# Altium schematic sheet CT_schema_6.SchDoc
size 411 x 402 mm
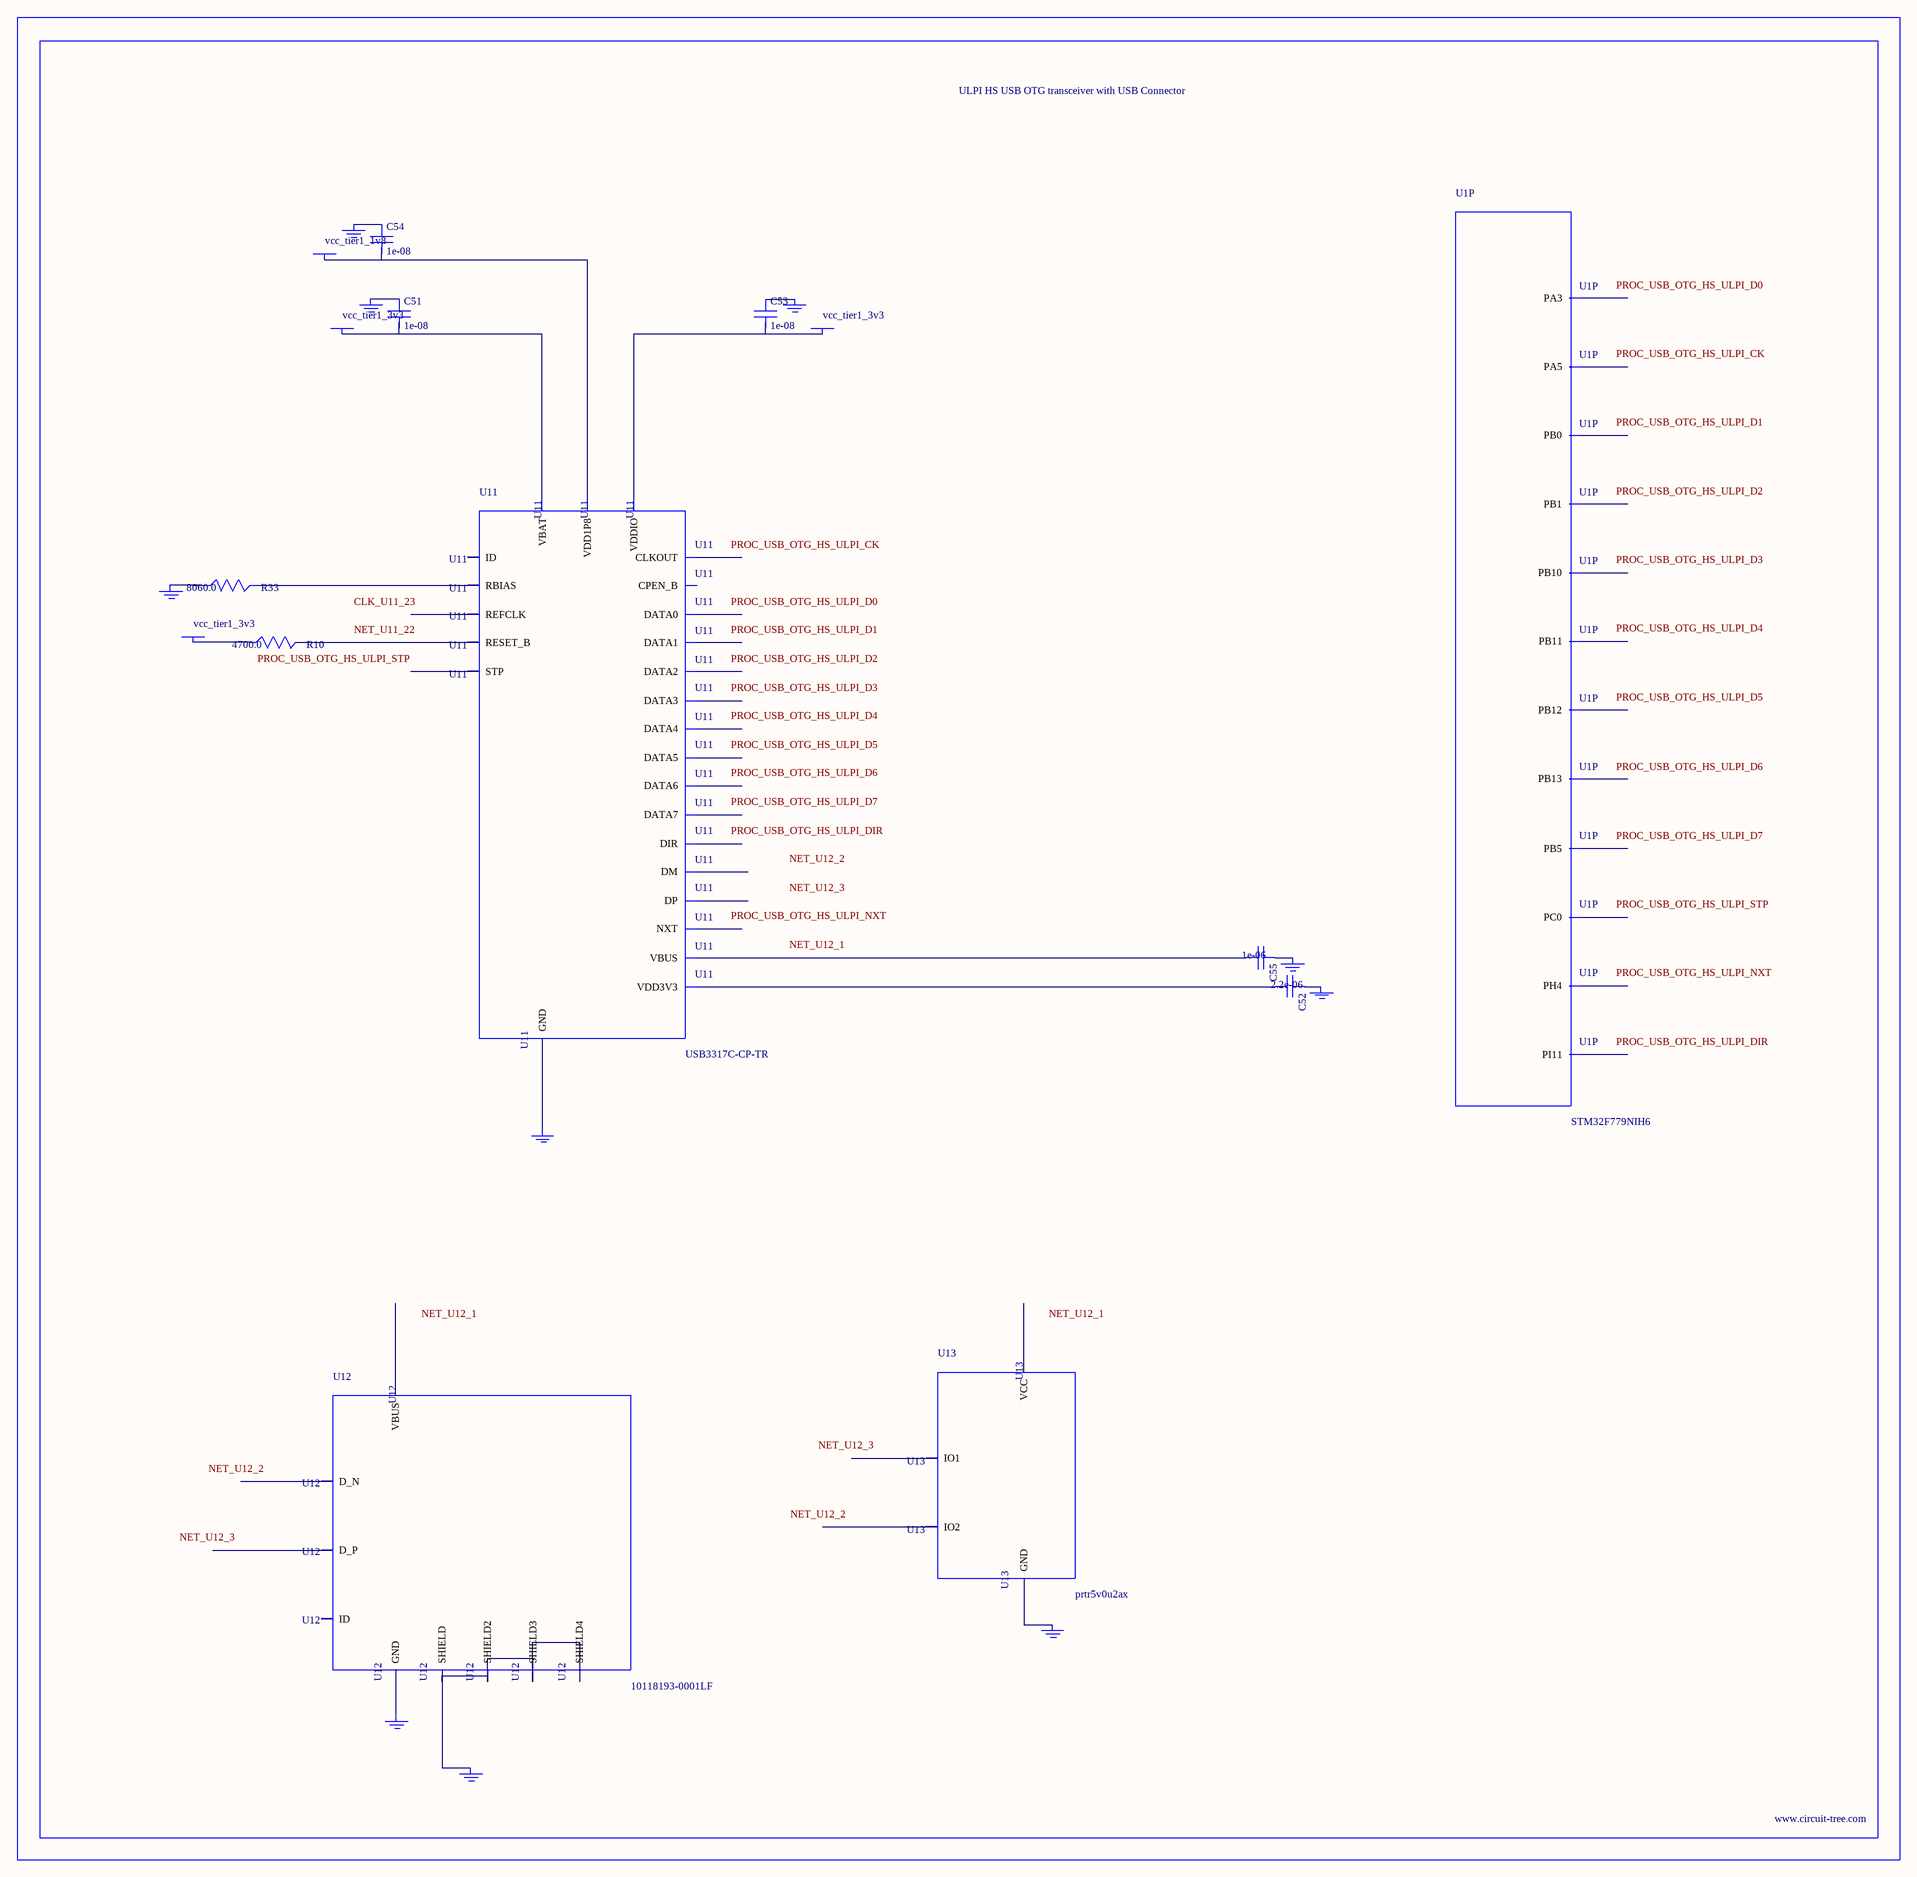
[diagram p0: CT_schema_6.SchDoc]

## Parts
BORDER5  (no value)
C51  1e-08  [C0402]
C52  2.2e-06  [C0603]
C53  1e-08  [C0402]
C54  1e-08  [C0402]
C55  1e-06  [C0603]
GND_INSTANCE_5_0  (no value)
GND_INSTANCE_5_1  (no value)
GND_INSTANCE_5_2  (no value)
GND_INSTANCE_5_3  (no value)
GND_INSTANCE_5_4  (no value)
GND_INSTANCE_5_5  (no value)
GND_INSTANCE_5_6  (no value)
GND_INSTANCE_5_7  (no value)
GND_INSTANCE_5_8  (no value)
GND_INSTANCE_5_9  (no value)
POWER_INSTANCE_5_0  vcc_tier1_3v3
POWER_INSTANCE_5_1  vcc_tier1_3v3
POWER_INSTANCE_5_2  vcc_tier1_1v8
POWER_INSTANCE_5_3  vcc_tier1_3v3
R10  4700.0  [R0603]
R33  8060.0  [R0603]
U1  STM32F779NIH6  [TFBGA216]  (part P of 16)
U11  USB3317C-CP-TR  [QFN-24]
U12  10118193-0001LF  [FCI_10118193-0001LF]
U13  prtr5v0u2ax  [SOT143B]

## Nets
NetC51_1: C51.1 GND_INSTANCE_5_1.0(GND)
NetC51_2: C51.2 POWER_INSTANCE_5_0.0(PWR) U11.3(VBAT)
NetC52_1: C52.1 GND_INSTANCE_5_2.0(GND)
NetC52_2: C52.2 U11.4(VDD3V3)
NetC53_1: C53.1 GND_INSTANCE_5_3.0(GND)
NetC53_2: C53.2 POWER_INSTANCE_5_1.0(PWR) U11.17(VDDIO)
NetC54_1: C54.1 GND_INSTANCE_5_4.0(GND)
NetC54_2: C54.2 POWER_INSTANCE_5_2.0(PWR) U11.21(VDD1P8)
NetC55_1: C55.1 GND_INSTANCE_5_0.0(GND)
NetC55_2: C55.2 U11.2(VBUS)
NetGND_INSTANCE_5_5_0: GND_INSTANCE_5_5.0(GND) R33.1
NetGND_INSTANCE_5_6_0: GND_INSTANCE_5_6.0(GND) U11.25(GND)
NetGND_INSTANCE_5_7_0: GND_INSTANCE_5_7.0(GND) U12.6(SHIELD) U12.7(SHIELD2) U12.8(SHIELD3) U12.9(SHIELD4)
NetGND_INSTANCE_5_8_0: GND_INSTANCE_5_8.0(GND) U12.5(GND)
NetGND_INSTANCE_5_9_0: GND_INSTANCE_5_9.0(GND) U13.1(GND)
NetPOWER_INSTANCE_5_3_0: POWER_INSTANCE_5_3.0(PWR) R10.1
NetR10_2: R10.2 U11.22(RESET_B)
NetR33_2: R33.2 U11.24(RBIAS)

Not connected (* = marked no-connect by the designer): U1 A8(PB5) F3(PI11) H4(PH4) K14(PB13) L13(PB12) M2(PC0) P4(PA5) P12(PB10) R2(PA3) R4(PB1) R5(PB0) R13(PB11); U11 1(ID) 5(DM) 6(DP) 7(CPEN_B) 8(DATA7) 9(DATA6) 10(DATA5) 11(DATA4) 12(CLKOUT) 13(DATA3) 14(DATA2) 15(DATA1) 16(DATA0) 18(NXT) 19(DIR) 20(STP) 23(REFCLK); U12 1(VBUS) 2(D_N) 3(D_P) 4(ID); U13 2(IO1) 3(IO2) 4(VCC)

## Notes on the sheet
- Labels drawn without touching a wire or pin: CLK_U11_23, NET_U11_22, NET_U12_1, NET_U12_2, NET_U12_3, PROC_USB_OTG_HS_ULPI_CK, PROC_USB_OTG_HS_ULPI_D0, PROC_USB_OTG_HS_ULPI_D1, PROC_USB_OTG_HS_ULPI_D2, PROC_USB_OTG_HS_ULPI_D3, PROC_USB_OTG_HS_ULPI_D4, PROC_USB_OTG_HS_ULPI_D5, PROC_USB_OTG_HS_ULPI_D6, PROC_USB_OTG_HS_ULPI_D7, PROC_USB_OTG_HS_ULPI_DIR, PROC_USB_OTG_HS_ULPI_NXT, PROC_USB_OTG_HS_ULPI_STP

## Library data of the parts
BORDER5 = BORDER_PAGE5
C51 C53 C54 = C0402C103K3RAC
C52 = C0603C225K8RACTU
C55 = C0603C105K3RACTU
GND_INSTANCE_5_0-GND_INSTANCE_5_9 = GND
POWER_INSTANCE_5_0-POWER_INSTANCE_5_3 = PWR
R10 = RC0603JR-074K7L
R33 = ERJ-3EKF8061V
